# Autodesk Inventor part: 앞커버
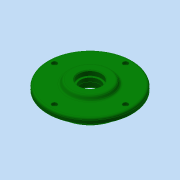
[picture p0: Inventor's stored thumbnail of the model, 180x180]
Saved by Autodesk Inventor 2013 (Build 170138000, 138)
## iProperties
Created: 2016-11
Part Number: 앞커버
Material: 알루미늄 6061
Document SubType Name: Modeling
Designer: mduedu
Density: 1 g/cm^3
Mass: 188.69 g
Surface Area: 365.029 cm^2
Volume: 188.69 cm^3
Author: mduedu
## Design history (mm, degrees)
sketch "스케치1"
  geometry: L1 (28.5, -17.5)-(28.5, -30); L2 (28.5, -30)-(22.5, -33.464); L3 (22.5, -33.464)-(22.5, -65); L4 (22.5, -65)-(14.5, -65); L5 (14.5, -65)-(14.5, -47.5); L6 (14.5, -47.5)-(0, -47.5); L7 (0, -47.5)-(0, -23.5); L8 (0, 0)-(28.5, 0); L9 (14.5, -23.5)-(14.5, -15); L10 (14.5, -15)-(20.5, -15); L11 (20.5, -15)-(20.5, -17.5); L12 (0, -23.5)-(14.5, -23.5); L13 (20.5, -17.5)-(28.5, -17.5)
  constraints: 26 end point, 8 parallel, 3 perpendicular, 2 horizontal, 2 vertical alignment, 1 collinear
  dimensions: "d0" = 14.5 distance of L5.end L6.end; "d2" = 8 distance of L3.end L4.end; "d3" = 6 distance between parallel lines of L1 L3; "d4" = 120 deg angle of L3 L2; "d5" = 8 distance of L11.end L1.start; "d6" = 60 diameter of L1.end L8; "d7" = 30 diameter of L10 L8; "d8" = 47 diameter of L12 L8; "d9" = 35 diameter of L13 L8; "d10" = 95 diameter of L6 L8; "d11" = 130 diameter of L4 L8
revolve "회전1" sketch "스케치1" stored, may be unused: angle "d12" = 90 deg
fillet "모깎기1" dims "d13" = 0.5
fillet "모깎기2" dims "d14" = 3
chamfer "모따기1" distance "d15" = 1; stored, may be unused: second distance "d16" = 2, angle "d17" = 45 deg
fillet "모깎기3" dims "d18" = 0.3
sketch "스케치2" dims "d19" = 110
  geometry: 6 further points
  constraints: 2 vertical alignment, 1 coincident, 7 other
  dimensions: "d22" = 360 deg dimension on point (0, 0) point (0, 55) (derived)
sketch "스케치3"
  geometry: 4 further points
  constraints: 4 other
hole "구멍1" sketch "스케치3" at (0, 55), (-55, 0), (55, 0), (0, -55) diameter "d24" = 4.5; stored, may be unused: countersink angle "d28" = 90 deg, drill point angle "d30" = 0 deg; dims "d25" = 6, "d26" = 8, "d27" = 4.6, "d29" = 8
node "솔리드1"
